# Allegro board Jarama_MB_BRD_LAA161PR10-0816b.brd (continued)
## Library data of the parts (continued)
Q347 = MMBT3904_SOT23-3
Q360 = SIS412DN-T1-GE3_POWERPAK8-5
Q361 = SI1553CDL-T1-GE3_SC70-6
R216 R1125 R1128 R1226 R1242 R1260 R1318-R1320 R1330 R1331 R1380 R1389 RA2 RA32 RH341 RH355 RH356 = R0603_0OHM
R541 = R_0805
R1221 R1222 R1372 RR2-RR5 RR7 RR8 RR12 RR13 RR15 RR16 = R0402_0OHM: signal model: R_0402NEW
R1322 RH340 = R0805_0OHM
RC92 RC96 = R0402_0OHM: signal model: R_0402NEW_R_0402NEW
RC94 = R_0402: signal model: R_0402NEW_R_0402NEW
RP3-RP5 RP21 RP22 = RP_0804_8P4R
RTCD1 = BAT54CW-7-F_SOT323-3
SW2 = SW_T3AL-23-Q-T-R_4P
T2 T123 T226-T231 T242-T246 T252 T254 T260 T261 T263-T289 = TPC12
U1 = RTS5227-GR_QFN32_4X4
U2 = W25Q32FVSSIQ_SO8
U4 = APA2605QAI-TRG_QFN20_4X4
U5 U682 U708-U710 U712 U713 = SN74AHC1G04DCKR_SOT23-5
U23 = PI3C3125LEX_TSSOP14
U34 = KB9012BF-A3_LFBGA_128P
U48 = W25Q64FVSSIQ_SO8
U635 = SN74LVC1G06DCKR_SC70-5
U636 = STM32F103RDY6TR_WLCSP_64P
U652 = AT97SC3204-X2A18-AB_TSSOP28
U663 = 74CBTLV3126BQ_DHVQFN14_2P5X3
U664 U715-U719 = TPS22966DPUR_SON14_2X3
U671 U677 = TXB0104PWR_TSSOP14
U672 UC1 = 74AUP1G07GW_TSSOP5
U673 = NCP4545IMNTWG_QFN18_3X3
U675 U678 U690 U691 U697 U698 UH5 = SN74AHC1G08DCKR_SC70-5
U676 = SN74CBT1G125DCKR_SC70-5
U679 = TXB0102YZPR_DSBGA_8P
U699 U700 = SN74AHC1G32DCKR_SC70-5
U714 = 1337GNLGI8_QFN16_3X3
U720 U721 U724 = TPS22965DSGR_SON8_2X2
U722 = PS8401ATQFN40GTR-A3_TQFN40_5X5
U725 = AH1806-W-7_SC59-3
UA1 = ALC5505_QFN48_7X7
UA2 = ALC3661-CG_MQFN48_6X6
UA3 = MAX9892ERTLFT_UCSP_6P
UCPU1 = SHARK-BAY-ULT_BGA_1168P-T
UD1 UD2 UD4-UD7 UD9 UD10 = MT41J256M16RE-15E-D_FBGA_96P
US1 US2 = TPS2543RTER_QFN16_3X3
Y1 YH1 = Y_CM31532768DZFT_2P
Y2 = Y_7A08000006_2P
Y3 = Y_Q13FC1350000200_2P
YA1 YH2 = Y_X3G024000DC1H_4P

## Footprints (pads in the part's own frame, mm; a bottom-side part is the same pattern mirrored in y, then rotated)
2N7002KDWH_SOT363-6
  oval 0.356x0.889 smd: 1(0,0) 2(0.65,0) 3(1.3,0) 4(1.3,1.6) 5(0.65,1.6) 6(0,1.6)
2N7002KW_SOT323-3
  oval 0.813x0.914 smd: 1(0,0) 2(0.65,1.6) 3(-0.65,1.6)
74AUP1G07GW_TSSOP5
  oval 0.381x1.346 smd: 1(0,0) 2(0.65,0) 3(1.3,0) 4(1.3,1.79) 5(0,1.79)
74CBTLV3126BQ_DHVQFN14_2P5X3
  oval 1.041x0.254 smd: 1(0,0) 7(2.95,0) 8(2.95,0.5) 14(0,0.5)
  oval 0.254x1.041 smd: 2(0.475,-0.975) 3(0.975,-0.975) 4(1.475,-0.975) 5(1.975,-0.975) 6(2.475,-0.975) 9(2.475,1.475) 10(1.975,1.475) 11(1.475,1.475) 12(0.975,1.475) 13(0.475,1.475)
  rect 1.499x0.991 smd: 15(1.475,0.25)
1337GNLGI8_QFN16_3X3
  oval 0.254x1.016 smd: 1(0,0) 2(0.5,0) 3(1,0) 4(1.5,0) 9(1.5,2.975) 10(1,2.975) 11(0.5,2.975) 12(0,2.975)
  oval 1.016x0.254 smd: 5(2.238,0.738) 6(2.238,1.238) 7(2.238,1.738) 8(2.238,2.238) 13(-0.738,2.238) 14(-0.738,1.738) 15(-0.738,1.238) 16(-0.738,0.738)
  rect 1.676x1.676 smd: 17(0.75,1.488)
ACES_50281-0120N-001_12P
  oval 0.787x2.007 smd: 1(0,0) 2(-1.25,0) 3(-2.5,0) 4(-3.75,0) 5(-5,0) 6(-6.25,0) 7(-7.5,0) 8(-8.75,0) 9(-10,0) 10(-11.25,0) 11(-12.5,0) 12(-13.75,0)
  rect 2.007x2.489 smd: 13(2.2,-4.05) 14(-15.95,-4.05)
ACES_50281-00501-001_5P-T
  oval 0.787x2.007 smd: 1(0,0) 2(1.25,0) 3(2.5,0) 4(3.75,0) 5(5,0)
  rect 2.007x2.489 smd: 6(7.2,-4.05) 7(-2.2,-4.05)
ACES_50406-02071-001_20P
  oval 0.254x1.295 smd: 1(0,0) 2(0.5,0) 3(1,0) 4(1.5,0) 5(2,0) 6(2.5,0) 7(3,0) 8(3.5,0) 9(4,0) 10(4.5,0) 11(5,0) 12(5.5,0) 13(6,0) 14(6.5,0) 15(7,0) 16(7.5,0) 17(8,0) 18(8.5,0) 19(9,0) 20(9.5,0)
  rect 1.194x2.692 smd: 21(-2.4,1.95) 22(11.9,1.95)
  rect 2.311x1.295 smd: 23(0.85,3.9) 24(8.65,3.9)
ACES_50696-02001-001_20P-T
  oval 0.305x0.787 smd: 1(0,0) 2(0.5,0) 3(1,0) 4(1.5,0) 5(2,0) 6(2.5,0) 7(3,0) 8(3.5,0) 9(4,0) 10(4.5,0) 11(5,0) 12(5.5,0) 13(6,0) 14(6.5,0) 15(7,0) 16(7.5,0) 17(8,0) 18(8.5,0) 19(9,0) 20(9.5,0)
  rect 0.406x0.787 smd: 21(-1,-2.5) 22(10.5,-2.5)
ACES_51522-00401-001_4P-T
  oval 0.305x1.295 smd: 1(0,0) 2(-0.5,0) 3(-1,0) 4(-1.5,0)
  rect 2.489x1.905 smd: 5(2.15,-3.3) 6(-3.65,-3.3)
ACES_51522-01001-001_10P
  oval 0.305x1.295 smd: 1(0,0) 2(0.5,0) 3(1,0) 4(1.5,0) 5(2,0) 6(2.5,0) 7(3,0) 8(3.5,0) 9(4,0) 10(4.5,0)
  rect 2.489x1.905 smd: 11(-2.15,-3.3) 12(6.65,-3.3)
ACES_51522-01201-001_12P
  oval 0.305x1.295 smd: 1(0,0) 2(0.5,0) 3(1,0) 4(1.5,0) 5(2,0) 6(2.5,0) 7(3,0) 8(3.5,0) 9(4,0) 10(4.5,0) 11(5,0) 12(5.5,0)
  rect 2.489x1.905 smd: 13(-2.15,-3.3) 14(7.65,-3.3)
ACON_HMR2G-AK120C_19P-T
  round 0.813 hole 0.559: 1(0,0) 2(-0.5,-1.55) 3(-1,0) 4(-1.5,-1.55) 5(-2,0) 6(-2.5,-1.55) 7(-3,0) 8(-3.5,-1.55) 9(-4,0) 10(-4.5,-1.55) 11(-5,0) 12(-5.5,-1.55) 13(-6,0) 14(-6.5,-1.55) 15(-7,0) 16(-7.5,-1.55) 17(-8,0) 18(-8.5,-1.55) 19(-9,0)
  oval 1.397x2.997 hole 0.787x2.388: 20(-11.75,-0.18) 21(2.75,-0.18)
  oval 1.397x2.794 hole 0.787x2.21: 22(-13.25,-7.53) 23(4.25,-7.53)
AH1806-W-7_SC59-3
  oval 0.787x0.991 smd: 1(0,0) 2(-0.95,-2.4) 3(0.95,-2.4)
ALC3661-CG_MQFN48_6X6
  oval 0.203x1.041 smd: 1(0,0) 2(0.4,0) 3(0.8,0) 4(1.2,0) 5(1.6,0) 6(2,0) 7(2.4,0) 8(2.8,0) 9(3.2,0) 10(3.6,0) 11(4,0) 12(4.4,0) 25(4.4,5.95) 26(4,5.95) 27(3.6,5.95) 28(3.2,5.95) 29(2.8,5.95) 30(2.4,5.95) 31(2,5.95) 32(1.6,5.95) 33(1.2,5.95) 34(0.8,5.95) 35(0.4,5.95) 36(0,5.95)
  oval 1.041x0.203 smd: 13(5.175,0.775) 14(5.175,1.175) 15(5.175,1.575) 16(5.175,1.975) 17(5.175,2.375) 18(5.175,2.775) 19(5.175,3.175) 20(5.175,3.575) 21(5.175,3.975) 22(5.175,4.375) 23(5.175,4.775) 24(5.175,5.175) 37(-0.775,5.175) 38(-0.775,4.775) 39(-0.775,4.375) 40(-0.775,3.975) 41(-0.775,3.575) 42(-0.775,3.175) 43(-0.775,2.775) 44(-0.775,2.375) 45(-0.775,1.975) 46(-0.775,1.575) 47(-0.775,1.175) 48(-0.775,0.775)
  rect 4.394x4.394 smd: 49(2.2,2.975)
ALC5505_QFN48_7X7
  oval 0.254x1.041 smd: 1(0,0) 2(0.5,0) 3(1,0) 4(1.5,0) 5(2,0) 6(2.5,0) 7(3,0) 8(3.5,0) 9(4,0) 10(4.5,0) 11(5,0) 12(5.5,0) 25(5.5,6.95) 26(5,6.95) 27(4.5,6.95) 28(4,6.95) 29(3.5,6.95) 30(3,6.95) 31(2.5,6.95) 32(2,6.95) 33(1.5,6.95) 34(1,6.95) 35(0.5,6.95) 36(0,6.95)
  oval 1.041x0.254 smd: 13(6.225,0.725) 14(6.225,1.225) 15(6.225,1.725) 16(6.225,2.225) 17(6.225,2.725) 18(6.225,3.225) 19(6.225,3.725) 20(6.225,4.225) 21(6.225,4.725) 22(6.225,5.225) 23(6.225,5.725) 24(6.225,6.225) 37(-0.725,6.225) 38(-0.725,5.725) 39(-0.725,5.225) 40(-0.725,4.725) 41(-0.725,4.225) 42(-0.725,3.725) 43(-0.725,3.225) 44(-0.725,2.725) 45(-0.725,2.225) 46(-0.725,1.725) 47(-0.725,1.225) 48(-0.725,0.725)
  rect 5.461x5.461 smd: 49(2.75,3.475)
AO3419L_SOT23-3
  oval 1.016x1.524 smd: 1(0,0) 2(0.965,2.083) 3(-0.965,2.083)
AO4407AL_SO8
  oval 0.635x1.854 smd: 1(0,0) 2(1.27,0) 3(2.54,0) 4(3.81,0) 5(3.81,5.165) 6(2.54,5.165) 7(1.27,5.165) 8(0,5.165)
APA2605QAI-TRG_QFN20_4X4
  oval 0.254x1.041 smd: 1(0,0) 2(0.5,0) 3(1,0) 4(1.5,0) 5(2,0) 11(2,3.95) 12(1.5,3.95) 13(1,3.95) 14(0.5,3.95) 15(0,3.95)
  oval 1.041x0.254 smd: 6(2.975,0.975) 7(2.975,1.475) 8(2.975,1.975) 9(2.975,2.475) 10(2.975,2.975) 16(-0.975,2.975) 17(-0.975,2.475) 18(-0.975,1.975) 19(-0.975,1.475) 20(-0.975,0.975)
  rect 2.261x2.261 smd: 21(1,1.975)
AT97SC3204-X2A18-AB_TSSOP28
  oval 0.381x1.626 smd: 1(0,0) 2(0.65,0) 3(1.3,0) 4(1.95,0) 5(2.6,0) 6(3.25,0) 7(3.9,0) 8(4.55,0) 9(5.2,0) 10(5.85,0) 11(6.5,0) 12(7.15,0) 13(7.8,0) 14(8.45,0) 15(8.45,5.8) 16(7.8,5.8) 17(7.15,5.8) 18(6.5,5.8) 19(5.85,5.8) 20(5.2,5.8) 21(4.55,5.8) 22(3.9,5.8) 23(3.25,5.8) 24(2.6,5.8) 25(1.95,5.8) 26(1.3,5.8) 27(0.65,5.8) 28(0,5.8)
AZ1045-04F_DFN2510P10E-10-9
  oval 0.254x0.686 smd: 1(0,0) 2(0.5,0) 4(1.5,0) 5(2,0) 6(2,0.875) 7(1.5,0.875) 8(0.5,0.875) 9(0,0.875)
  oval 0.406x1.549 smd: 3(1,0.437)
AZ1065-06QPRDG_MSOP8
  oval 0.381x1.575 smd: 1(0,0) 2(0.65,0) 3(1.3,0) 4(1.95,0) 5(1.95,4.35) 6(1.3,4.35) 7(0.65,4.35) 8(0,4.35)
BAT54CW-7-F_SOT323-3
  oval 0.711x0.889 smd: 1(0,0) 2(-0.65,-1.9) 3(0.65,-1.9)
BAT54CW_SOT323-3
  oval 0.61x0.559 smd: 1(0,0) 2(-0.65,-1.85) 3(0.65,-1.85)
BAT54HT1G_SOD323-2
  rect 0.635x0.838 smd: 1(0,0) 2(2.22,0)
BAT1000-7-F_SOT23-3
  oval 1.016x1.524 smd: 1(0,0) 2(0.965,2.083) 3(-0.965,2.083)
BJ_CR2016-L01-JHLF_2P
  rect 1.245x2.489 smd: 1(0,0) 2(6.25,0)
BQ24715RGRR_QFN20_3P5X3P5
  oval 0.254x1.041 smd: 1(0,0) 2(0.5,0) 3(1,0) 4(1.5,0) 5(2,0) 11(2,3.45) 12(1.5,3.45) 13(1,3.45) 14(0.5,3.45) 15(0,3.45)
  oval 1.041x0.254 smd: 6(2.725,0.725) 7(2.725,1.225) 8(2.725,1.725) 9(2.725,2.225) 10(2.725,2.725) 16(-0.725,2.725) 17(-0.725,2.225) 18(-0.725,1.725) 19(-0.725,1.225) 20(-0.725,0.725)
  rect 2.057x2.057 smd: 21(1,1.725)
C_0402
  rect 0.508x0.559 smd: 1(0,0) 2(0.914,0)
C_0603
  rect 0.635x0.889 smd: 1(0,0) 2(1.397,0)
C_0805
  rect 0.813x1.397 smd: 1(0,0) 2(1.702,0)
C_1206
  rect 1.016x1.651 smd: 1(0,0) 2(2.667,0)
C_A1
  rect 1.346x1.499 smd: 1(0,0) 2(2.45,0)
C_B
  rect 1.549x2.464 smd: 1(0,0) 2(3.378,0)
C_B2
  rect 1.346x2.692 smd: 1(0,0) 2(-2.75,0)
CSD87312Q3E_SON8-4
  rect 2.388x0.66 smd: 1(0,0)
  rect 0.432x0.66 smd: 2(0.975,2.95)
  rect 1.753x0.66 smd: 3(-0.325,2.95)
  custom 0.475x0.475 smd: 4(0,1.475)
CSD87330Q3D_SON8-7
  oval 1.092x0.66 smd: 1(0,0)
  oval 0.432x0.66 smd: 2(0.975,0) 3(1.625,0) 4(1.625,2.95) 5(0.975,2.95) 6(0.325,2.95) 7(-0.325,2.95)
  custom 0.475x0.475 smd: 8(0.65,1.475)
CSD97374CQ4M_SON8_3P5X4P5
  oval 0.203x0.889 smd: 1(0,0) 2(0.4,0) 3(0.8,0) 6(0.8,3.5) 7(0.4,3.5) 8(0,3.5)
  custom 0.225x0.225 smd: 4(2.2,0.262) 5(2.2,3.238)
  rect 4.039x2.21 smd: 9(1.6,1.75)
CVILU_CI4304M2HR0-NH_4P
  oval 0.787x2.007 smd: 1(0,0) 2(1.25,0) 3(2.5,0) 4(3.75,0)
  rect 2.007x2.489 smd: 5(-2.2,-4.05) 6(5.95,-4.05)
CYNTE_PCMB063T-2R2MS_2P
  rect 2.362x3.505 smd: 1(0,0) 2(6.05,0)
CYNTE_PCMC063T-R68MN_2P
  rect 1.854x3.505 smd: 1(0,0) 2(5.55,0)
CYNTE_PG031B-4R7MS_2P
  rect 0.889x1.194 smd: 1(0,0) 2(2.2,0)
DB2J31400L_SOD323-2
  rect 0.991x1.092 smd: 1(0,0)
  rect 0.991x0.889 smd: 2(2.1,0)
DMN66D0LDW-7_SOT363-6
  oval 0.432x0.61 smd: 1(0,0) 2(0.65,0) 3(1.3,0) 4(1.3,1.9) 5(0.65,1.9) 6(0,1.9)
E-T_6705K-Y18N-00L_18P
  oval 0.305x1.092 smd: 1(0,0) 2(-0.5,0) 3(-1,0) 4(-1.5,0) 5(-2,0) 6(-2.5,0) 7(-3,0) 8(-3.5,0) 9(-4,0) 10(-4.5,0) 11(-5,0) 12(-5.5,0) 13(-6,0) 14(-6.5,0) 15(-7,0) 16(-7.5,0) 17(-8,0) 18(-8.5,0)
  rect 0.991x2.007 smd: 19(2.1,-3.15) 20(-10.6,-3.15)
F_1812L075-24DR
  rect 0.889x3.15 smd: 1(0,0) 2(4.35,0)
F_SMD1812P110TF
  rect 0.889x3.15 smd: 1(0,0) 2(4.35,0)
FDV301N-G_SOT23-3
  oval 1.016x1.524 smd: 1(0,0) 2(0.965,2.083) 3(-0.965,2.083)
FIDUCIAL_C40M80
  round 1.016 smd: 1(0,0)
FOX_GS73091-10272-7H_9P-T
  rect 0.66x5.004 smd: 1(0,0) 2(-1.5,0) 3(-3,0) 4(-4.5,0) 5(-6,0) 6(-7.5,0) 7(-9,0) 8(-10.5,0) 9(-12,0)
  rect 2.489x2.997 smd: 10(-14.5,4.45) 11(2.5,4.45)
G5616ARZ1U_TQFN20_3X3
  oval 0.203x1.016 smd: 1(0,0) 2(0.4,0) 3(0.8,0) 4(1.2,0) 5(1.6,0) 11(1.6,2.975) 12(1.2,2.975) 13(0.8,2.975) 14(0.4,2.975) 15(0,2.975)
  oval 1.016x0.203 smd: 6(2.288,0.688) 7(2.288,1.088) 8(2.288,1.488) 9(2.288,1.888) 10(2.288,2.288) 16(-0.688,2.288) 17(-0.688,1.888) 18(-0.688,1.488) 19(-0.688,1.088) 20(-0.688,0.688)
  rect 1.6x1.6 smd: 21(0.8,1.488)
H_1P6N
  round 1.6 hole 1.6 unplated: (0,0)
H_2P4
  round 2.896 hole 2.388: 1(0,0)
H_2P4X1P6N
  oval 2.388x1.6 hole 2.388x1.6 unplated: (0,0)
H_3P0
  round 3.505 hole 2.997: 1(0,0)
H_3P3
  round 3.81 hole 3.302: 1(0,0)
H_3P9
  round 4.42 hole 3.912: 1(0,0)
HB_A510810-SCHR21_8P
  oval 0.305x1.092 smd: 1(0,0) 2(-0.5,0) 3(-1,0) 4(-1.5,0) 5(-2,0) 6(-2.5,0) 7(-3,0) 8(-3.5,0)
  rect 0.406x0.787 smd: 9(-4.5,-2.65) 10(1,-2.65)
HB_A520620-SCHR22_6P
  oval 0.305x1.295 smd: 1(0,0) 2(0.5,0) 3(1,0) 4(1.5,0) 5(2,0) 6(2.5,0)
  rect 2.489x1.905 smd: 7(-2.15,-3.3) 8(4.65,-3.3)
HB_A531515-SCHR21_15P-T
  oval 0.305x1.245 smd: 1(0,0) 2(0.5,0) 3(1,0) 4(1.5,0) 5(2,0) 6(2.5,0) 7(3,0) 8(3.5,0) 9(4,0) 10(4.5,0) 11(5,0) 12(5.5,0) 13(6,0) 14(6.5,0) 15(7,0)
  rect 0.991x2.007 smd: 16(-2.1,-2.875) 17(9.1,-2.875)
IP4223CZ6_SO6
  oval 0.508x1.422 smd: 1(0,0) 2(0.95,0) 3(1.9,0) 4(1.9,2.35) 5(0.95,2.35) 6(0,2.35)
JAE_SM3ZS067U215ALL_75P-T
  round 1.092 hole 1.092 unplated: (-0.75,-5.225)
  round 1.6 hole 1.6 unplated: (19.25,-5.225)
  oval 0.305x1.549 smd: 1(0,0) 2(0.25,-7.45) 3(0.5,0) 4(0.75,-7.45) 5(1,0) 6(1.25,-7.45) 7(1.5,0) 8(1.75,-7.45) 9(2,0) 10(2.25,-7.45) 11(2.5,0) 12(2.75,-7.45) 13(3,0) 14(3.25,-7.45) 15(3.5,0) 16(3.75,-7.45) 17(4,0) 18(4.25,-7.45) 19(4.5,0) 20(4.75,-7.45) 21(5,0) 22(5.25,-7.45) 23(5.5,0) 24(5.75,-7.45) 25(6,0) 26(6.25,-7.45) 27(6.5,0) 28(6.75,-7.45) 29(7,0) 30(7.25,-7.45) 31(7.5,0) 32(7.75,-7.45) 33(8,0) 34(8.25,-7.45) 35(8.5,0) 36(8.75,-7.45) 37(9,0) 38(9.25,-7.45) 39(9.5,0) 40(9.75,-7.45) 41(10,0) 42(10.25,-7.45) 43(10.5,0) 44(10.75,-7.45) 45(11,0) 46(11.25,-7.45) 47(11.5,0) 48(11.75,-7.45) 49(12,0) 50(12.25,-7.45) 51(12.5,0) 52(12.75,-7.45) 53(13,0) 54(13.25,-7.45) 55(13.5,0) 56(13.75,-7.45) 57(14,0) 58(14.25,-7.45) 59(14.5,0) 60(14.75,-7.45) 61(15,0) 62(15.25,-7.45) 63(15.5,0) 64(15.75,-7.45) 65(16,0) 66(16.25,-7.45) 67(16.5,0) 68(16.75,-7.45) 69(17,0) 70(17.25,-7.45) 71(17.5,0) 72(17.75,-7.45) 73(18,0) 74(18.25,-7.45) 75(18.5,0)
  rect 1.194x2.743 smd: 76(19.6,-0.725) 77(-1.1,-0.725)
JUMP_43X39
  custom 0.191x0.191 smd: 1(0,0) 2(0.914,0)
JUMP_43X79
  custom 0.188x0.188 smd: 1(0,0) 2(1.1,0)
JUMP_43X118
  custom 0.187x0.187 smd: 1(0,0) 2(1.1,0)
KB9012BF-A3_LFBGA_128P
  round 0.254 smd: A1(0,0) A2(0.5,0) A3(1,0) A4(1.5,0) A5(2,0) A6(2.5,0) A7(3,0) A8(3.5,0) A9(4,0) A10(4.5,0) A11(5,0) A12(5.5,0) A13(6,0) B1(0,-0.5) B2(0.5,-0.5) B3(1,-0.5) B4(1.5,-0.5) B5(2,-0.5) B6(2.5,-0.5) B7(3,-0.5) B8(3.5,-0.5) B9(4,-0.5) B10(4.5,-0.5) B11(5,-0.5) B12(5.5,-0.5) B13(6,-0.5) C1(0,-1) C2(0.5,-1) C12(5.5,-1) C13(6,-1) D1(0,-1.5) D2(0.5,-1.5) D4(1.5,-1.5) D5(2,-1.5) D6(2.5,-1.5) D7(3,-1.5) D8(3.5,-1.5) D9(4,-1.5) D10(4.5,-1.5) D12(5.5,-1.5) D13(6,-1.5) E1(0,-2) E2(0.5,-2) E4(1.5,-2) E5(2,-2) E6(2.5,-2) E7(3,-2) E8(3.5,-2) E9(4,-2) E10(4.5,-2) E12(5.5,-2) E13(6,-2) F1(0,-2.5) F2(0.5,-2.5) F4(1.5,-2.5) F5(2,-2.5) F9(4,-2.5) F10(4.5,-2.5) F12(5.5,-2.5) F13(6,-2.5) G1(0,-3) G2(0.5,-3) G4(1.5,-3) G5(2,-3) G9(4,-3) G10(4.5,-3) G12(5.5,-3) G13(6,-3) H1(0,-3.5) H2(0.5,-3.5) H4(1.5,-3.5) H5(2,-3.5) H9(4,-3.5) H10(4.5,-3.5) H12(5.5,-3.5) H13(6,-3.5) J1(0,-4) J2(0.5,-4) J4(1.5,-4) J5(2,-4) J6(2.5,-4) J7(3,-4) J8(3.5,-4) J9(4,-4) J10(4.5,-4) J12(5.5,-4) J13(6,-4) K1(0,-4.5) K2(0.5,-4.5) K4(1.5,-4.5) K5(2,-4.5) K6(2.5,-4.5) K7(3,-4.5) K8(3.5,-4.5) K9(4,-4.5) K10(4.5,-4.5) K12(5.5,-4.5) K13(6,-4.5) L1(0,-5) L2(0.5,-5) L12(5.5,-5) L13(6,-5) M1(0,-5.5) M2(0.5,-5.5) M3(1,-5.5) M4(1.5,-5.5) M5(2,-5.5) M6(2.5,-5.5) M7(3,-5.5) M8(3.5,-5.5) M9(4,-5.5) M10(4.5,-5.5) M11(5,-5.5) M12(5.5,-5.5) M13(6,-5.5) N1(0,-6) N2(0.5,-6) N3(1,-6) N4(1.5,-6) N5(2,-6) N6(2.5,-6) N7(3,-6) N8(3.5,-6) N9(4,-6) N10(4.5,-6) N11(5,-6) N12(5.5,-6) N13(6,-6)
KC_FBMA-L11-160808-800LMT_2P
  rect 0.889x1.092 smd: 1(0,0) 2(1.5,0)
KC_FBMA-L11-201209-121LMA50_2P
  rect 0.991x1.702 smd: 1(0,0) 2(1.5,0)
KC_FBMA-L11-453215800LMA90T_2P
  rect 1.803x3.404 smd: 1(0,0) 2(3.8,0)
LCN_DAN08-52216-0100_52P
  round 0.991 hole 0.991 unplated: (-26.2,-3) (2.6,-3)
  oval 0.406x1.6 smd: 1(0,0) 3(-0.8,0) 5(-1.6,0) 7(-2.4,0) 9(-3.2,0) 11(-4,0) 13(-4.8,0) 15(-5.6,0) 17(-9.6,0) 19(-10.4,0) 21(-11.2,0) 23(-12,0) 25(-12.8,0) 27(-13.6,0) 29(-14.4,0) 31(-15.2,0) 33(-16,0) 35(-16.8,0) 37(-17.6,0) 39(-18.4,0) 41(-19.2,0) 43(-20,0) 45(-20.8,0) 47(-21.6,0) 49(-22.4,0) 51(-23.2,0)
  oval 0.61x1.397 hole 0.406x0.787: 2(-0.4,-1.65) 4(-1.2,-1.65) 6(-2,-1.65) 8(-2.8,-1.65) 10(-3.6,-1.65) 12(-4.4,-1.65) 14(-5.2,-1.65) 16(-6,-1.65) 18(-10,-1.65) 20(-10.8,-1.65) 22(-11.6,-1.65) 24(-12.4,-1.65) 26(-13.2,-1.65) 28(-14,-1.65) 30(-14.8,-1.65) 32(-15.6,-1.65) 34(-16.4,-1.65) 36(-17.2,-1.65) 38(-18,-1.65) 40(-18.8,-1.65) 42(-19.6,-1.65) 44(-20.4,-1.65) 46(-21.2,-1.65) 48(-22,-1.65) 50(-22.8,-1.65) 52(-23.6,-1.65)
  oval 1.27x2.972 hole 0.508x2.21: 53(3.1,-6.2) 54(-26.7,-6.2)
LED_LTW-C193TS5_2P
  rect 0.787x0.787 smd: 1(0,0) 2(1.5,0)
LOTES_APCI0019-P001A01_67P-T
  round 1.092 hole 1.092 unplated: (-0.75,-5.275)
  round 1.6 hole 1.6 unplated: (19.25,-5.275)
  oval 0.305x1.549 smd: 1(0,0) 2(0.25,-7.55) 3(0.5,0) 4(0.75,-7.55) 5(1,0) 6(1.25,-7.55) 7(1.5,0) 8(1.75,-7.55) 9(2,0) 10(2.25,-7.55) 11(2.5,0) 12(2.75,-7.55) 13(3,0) 14(3.25,-7.55) 15(3.5,0) 16(3.75,-7.55) 17(4,0) 18(4.25,-7.55) 19(4.5,0) 20(4.75,-7.55) 21(5,0) 22(5.25,-7.55) 23(5.5,0) 24(7.75,-7.55) 25(8,0) 26(8.25,-7.55) 27(8.5,0) 28(8.75,-7.55) 29(9,0) 30(9.25,-7.55) 31(9.5,0) 32(9.75,-7.55) 33(10,0) 34(10.25,-7.55) 35(10.5,0) 36(10.75,-7.55) 37(11,0) 38(11.25,-7.55) 39(11.5,0) 40(11.75,-7.55) 41(12,0) 42(12.25,-7.55) 43(12.5,0) 44(12.75,-7.55) 45(13,0) 46(13.25,-7.55) 47(13.5,0) 48(13.75,-7.55) 49(14,0) 50(14.25,-7.55) 51(14.5,0) 52(14.75,-7.55) 53(15,0) 54(15.25,-7.55) 55(15.5,0) 56(15.75,-7.55) 57(16,0) 58(16.25,-7.55) 59(16.5,0) 60(16.75,-7.55) 61(17,0) 62(17.25,-7.55) 63(17.5,0) 64(17.75,-7.55) 65(18,0) 66(18.25,-7.55) 67(18.5,0)
  rect 1.194x2.743 smd: 68(-1.1,-0.775) 69(19.6,-0.775)
MAG_MMD06CZER15MG_4P
  custom 0.686x0.686 smd: 1(0,0) 4(8.509,0)
  rect 2.362x0.508 smd: 2(1.448,0) 3(7.061,0)
MAX9892ERTLFT_UCSP_6P
  round 0.267 smd: A1(0,0) A2(0.5,0) A3(1,0) B1(0,-0.5) B2(0.5,-0.5) B3(1,-0.5)
MDV1524URH_PDFN33-8-5
  oval 0.406x0.61 smd: 1(0,0) 2(0.65,0) 3(1.3,0) 4(1.95,0)
  custom 0.65x0.65 smd: 5(0.975,1.475)
MDV1528URH_PDFN33-8-5
  oval 0.406x0.61 smd: 1(0,0) 2(0.65,0) 3(1.3,0) 4(1.95,0)
  custom 0.65x0.65 smd: 5(0.975,1.475)
MMBT3904_SOT23-3
  oval 1.016x1.524 smd: 1(0,0) 2(0.965,2.083) 3(-0.965,2.083)
MMST3904-7-F_SOT323-3
  oval 0.711x0.889 smd: 1(0,0) 2(0.65,1.9) 3(-0.65,1.9)
MT41J256M16RE-15E-D_FBGA_96P
  round 0.343 smd: A1(0,0) A2(0.8,0) A3(1.6,0) A7(4.8,0) A8(5.6,0) A9(6.4,0) B1(0,-0.8) B2(0.8,-0.8) B3(1.6,-0.8) B7(4.8,-0.8) B8(5.6,-0.8) B9(6.4,-0.8) C1(0,-1.6) C2(0.8,-1.6) C3(1.6,-1.6) C7(4.8,-1.6) C8(5.6,-1.6) C9(6.4,-1.6) D1(0,-2.4) D2(0.8,-2.4) D3(1.6,-2.4) D7(4.8,-2.4) D8(5.6,-2.4) D9(6.4,-2.4) E1(0,-3.2) E2(0.8,-3.2) E3(1.6,-3.2) E7(4.8,-3.2) E8(5.6,-3.2) E9(6.4,-3.2) F1(0,-4) F2(0.8,-4) F3(1.6,-4) F7(4.8,-4) F8(5.6,-4) F9(6.4,-4) G1(0,-4.8) G2(0.8,-4.8) G3(1.6,-4.8) G7(4.8,-4.8) G8(5.6,-4.8) G9(6.4,-4.8) H1(0,-5.6) H2(0.8,-5.6) H3(1.6,-5.6) H7(4.8,-5.6) H8(5.6,-5.6) H9(6.4,-5.6) J1(0,-6.4) J2(0.8,-6.4) J3(1.6,-6.4) J7(4.8,-6.4) J8(5.6,-6.4) J9(6.4,-6.4) K1(0,-7.2) K2(0.8,-7.2) K3(1.6,-7.2) K7(4.8,-7.2) K8(5.6,-7.2) K9(6.4,-7.2) L1(0,-8) L2(0.8,-8) L3(1.6,-8) L7(4.8,-8) L8(5.6,-8) L9(6.4,-8) M1(0,-8.8) M2(0.8,-8.8) M3(1.6,-8.8) M7(4.8,-8.8) M8(5.6,-8.8) M9(6.4,-8.8) N1(0,-9.6) N2(0.8,-9.6) N3(1.6,-9.6) N7(4.8,-9.6) N8(5.6,-9.6) N9(6.4,-9.6) P1(0,-10.4) P2(0.8,-10.4) P3(1.6,-10.4) P7(4.8,-10.4) P8(5.6,-10.4) P9(6.4,-10.4) R1(0,-11.2) R2(0.8,-11.2) R3(1.6,-11.2) R7(4.8,-11.2) R8(5.6,-11.2) R9(6.4,-11.2) T1(0,-12) T2(0.8,-12) T3(1.6,-12) T7(4.8,-12) T8(5.6,-12) T9(6.4,-12)
MURAT_BLM15AG102SN1D_2P
  rect 0.457x0.508 smd: 1(0,0) 2(0.85,0)
MURAT_BLM18BA220SN1D_2P
  oval 0.66x1.041 smd: 1(0,0) 2(1.2,0)
MURAT_BLM18PG181SN1D_L0603_2P
  rect 0.66x1.041 smd: 1(0,0) 2(1.2,0)
MURAT_BLM21PG600SN1D_2P
  rect 0.991x1.753 smd: 1(0,0) 2(1.5,0)
MURAT_DLW21HN900SQ2L_4P
  rect 0.889x0.356 smd: 1(0,0) 2(1.7,0) 3(1.7,0.85) 4(0,0.85)
MURAT_DLW21SN670HQ2L_4P
  rect 0.889x0.406 smd: 1(0,0) 2(1.7,0) 3(1.7,0.8) 4(0,0.8)
MURAT_DLW21SN900HQ2L_0805_4P
  rect 0.889x0.356 smd: 1(0,0) 2(1.7,0) 3(1.7,0.85) 4(0,0.85)
MURAT_LQM2MPN2R2NG0L_2P
  rect 0.787x1.803 smd: 1(0,0) 2(1.6,0)
NCP4545IMNTWG_QFN18_3X3
  oval 0.254x0.94 smd: 1(0,0) 2(0.5,0) 3(1,0) 4(1.5,0) 10(1.5,3.05) 11(1,3.05) 12(0.5,3.05) 13(0,3.05)
  oval 0.94x0.254 smd: 5(2.275,0.525) 6(2.275,1.025) 7(2.275,1.525) 8(2.275,2.025) 9(2.275,2.525) 14(-0.775,2.525) 15(-0.775,2.025) 16(-0.775,1.525) 17(-0.775,1.025) 18(-0.775,0.525)
  rect 1.854x1.854 smd: 19(0.75,1.525)
NCQF0_MB_SUP_BRK
  custom 1.25x1.25 smd: 1(0,0)
PESD5V0U2BT_SOT23-3
  oval 1.016x1.524 smd: 1(0,0) 2(0.965,2.083) 3(-0.965,2.083)
PESD24VS2UT_SOT23-3
  oval 1.016x1.524 smd: 1(0,0) 2(0.965,2.083) 3(-0.965,2.083)
PI3C3125LEX_TSSOP14
  oval 0.381x1.626 smd: 1(0,0) 2(0.65,0) 3(1.3,0) 4(1.95,0) 5(2.6,0) 6(3.25,0) 7(3.9,0) 8(3.9,5.8) 9(3.25,5.8) 10(2.6,5.8) 11(1.95,5.8) 12(1.3,5.8) 13(0.65,5.8) 14(0,5.8)
PJDLC05_SOT23-3
  oval 1.016x1.524 smd: 1(0,0) 2(0.965,2.083) 3(-0.965,2.083)
PJDLC05C_SOT23-3
  oval 1.016x1.524 smd: 1(0,0) 2(0.965,2.083) 3(-0.965,2.083)
PS8401ATQFN40GTR-A3_TQFN40_5X5
  oval 0.203x1.016 smd: 1(0,0) 2(0.4,0) 3(0.8,0) 4(1.2,0) 5(1.6,0) 6(2,0) 7(2.4,0) 8(2.8,0) 9(3.2,0) 10(3.6,0) 21(3.6,4.975) 22(3.2,4.975) 23(2.8,4.975) 24(2.4,4.975) 25(2,4.975) 26(1.6,4.975) 27(1.2,4.975) 28(0.8,4.975) 29(0.4,4.975) 30(0,4.975)
  oval 1.016x0.203 smd: 11(4.288,0.688) 12(4.288,1.088) 13(4.288,1.488) 14(4.288,1.888) 15(4.288,2.288) 16(4.288,2.688) 17(4.288,3.088) 18(4.288,3.488) 19(4.288,3.888) 20(4.288,4.288) 31(-0.688,4.288) 32(-0.688,3.888) 33(-0.688,3.488) 34(-0.688,3.088) 35(-0.688,2.688) 36(-0.688,2.288) 37(-0.688,1.888) 38(-0.688,1.488) 39(-0.688,1.088) 40(-0.688,0.688)
  rect 3.607x3.607 smd: 41(1.8,2.488)
R0402_0OHM
  rect 0.508x0.559 smd: 1(0,0) 2(0.914,0)
R0603_0OHM
  rect 0.635x0.889 smd: 1(0,0) 2(1.397,0)
R0805_0OHM
  rect 0.813x1.397 smd: 1(0,0) 2(1.702,0)
R_0402
  rect 0.508x0.559 smd: 1(0,0) 2(0.914,0)
R_0603
  rect 0.635x0.889 smd: 1(0,0) 2(1.397,0)
R_0805
  rect 0.813x1.397 smd: 1(0,0) 2(1.702,0)
R_1206
  rect 1.016x1.651 smd: 1(0,0) 2(2.667,0)
R_1206_4P-D
  custom 0.445x0.445 smd: 1(0,0) 4(5.004,0)
  custom 0.114x0.114 smd: 2(1.194,0) 3(3.81,0)
RB751V-40_SOD323-2
  rect 0.787x0.889 smd: 1(0,0) 2(2.14,0)
RB751V-40GTE-17_SOD323-2
  rect 0.787x0.889 smd: 1(0,0) 2(2.1,0)
RP_0804_8P4R
  oval 0.66x0.254 smd: 1(0,0) 2(0,-0.5) 3(0,-1) 4(0,-1.5) 5(1.15,-1.5) 6(1.15,-1) 7(1.15,-0.5) 8(1.15,0)
RTS5227-GR_QFN32_4X4
  oval 0.203x0.914 smd: 1(0,0) 2(0.4,0) 3(0.8,0) 4(1.2,0) 5(1.6,0) 6(2,0) 7(2.4,0) 8(2.8,0) 17(2.8,4.077) 18(2.4,4.077) 19(2,4.077) 20(1.6,4.077) 21(1.2,4.077) 22(0.8,4.077) 23(0.4,4.077) 24(0,4.077)
  oval 0.914x0.203 smd: 9(3.438,0.639) 10(3.438,1.039) 11(3.438,1.438) 12(3.438,1.838) 13(3.438,2.239) 14(3.438,2.639) 15(3.438,3.039) 16(3.438,3.438) 25(-0.639,3.438) 26(-0.639,3.039) 27(-0.639,2.639) 28(-0.639,2.239) 29(-0.639,1.838) 30(-0.639,1.438) 31(-0.639,1.039) 32(-0.639,0.639)
  rect 2.692x2.692 smd: 33(1.4,2.039)
SAMTE_BSH-030-01-L-D-A_60P
  round 1.016 hole 1.016 unplated: (-2.81,5.53) (17.316,5.53)
  oval 0.279x2.261 smd: 1(0,0) 2(0,5.728) 3(0.5,0) 4(0.5,5.728) 5(1,0) 6(1,5.728) 7(1.5,0) 8(1.5,5.728) 9(2,0) 10(2,5.728) 11(2.5,0) 12(2.5,5.728) 13(3,0) 14(3,5.728) 15(3.5,0) 16(3.5,5.728) 17(4,0) 18(4,5.728) 19(4.5,0) 20(4.5,5.728) 21(5,0) 22(5,5.728) 23(5.5,0) 24(5.5,5.728) 25(6,0) 26(6,5.728) 27(6.5,0) 28(6.5,5.728) 29(7,0) 30(7,5.728) 31(7.5,0) 32(7.5,5.728) 33(8,0) 34(8,5.728) 35(8.5,0) 36(8.5,5.728) 37(9,0) 38(9,5.728) 39(9.5,0) 40(9.5,5.728) 41(10,0) 42(10,5.728) 43(10.5,0) 44(10.5,5.728) 45(11,0) 46(11,5.728) 47(11.5,0) 48(11.5,5.728) 49(12,0) 50(12,5.728) 51(12.5,0) 52(12.5,5.728) 53(13,0) 54(13,5.728) 55(13.5,0) 56(13.5,5.728) 57(14,0) 58(14,5.728) 59(14.5,0) 60(14.5,5.728)
SDMK0340L-7-F_SOD323-2
  rect 1.346x0.66 smd: 1(0,0) 2(2.4,0)
SHARK-BAY-ULT_BGA_1168P-T
  round 0.508 smd: A3(-1.137,0) A62(-38.036,0) AW1(0,22.042) AW63(-38.628,22.057) AY2(-0.543,22.628) AY62(-38.062,22.628) B2(-0.508,0.508) B63(-38.628,0.592) C1(0,1.137)
  round 0.381 smd: A4(-1.894,0) A5(-2.554,0) A6(-3.75,0) A59(-35.9,0) A60(-36.726,0) A61(-37.386,0) AA9(-5.032,11.576) AA21(-11.688,11.489) AA23(-13.115,11.489) AA58(-35.377,11.33) AB10(-5.476,12.053) AB20(-11.18,11.896) AB21(-11.688,12.302) AB22(-12.607,11.896) AB23(-13.115,12.302) AB57(-35.057,11.98) AC9(-5.032,12.529) AC20(-11.18,12.709) AC22(-12.607,12.709) AC58(-35.377,12.63) AD10(-5.476,13.005) AD21(-11.688,13.115) AD23(-13.115,13.115) AD57(-35.057,13.28) AE9(-5.032,13.481) AE10(-5.476,13.958) AE20(-11.18,13.521) AE21(-11.688,13.928) AE22(-12.607,13.521) AE23(-13.115,13.928) AE58(-35.377,13.931) AF9(-5.032,14.434) AF11(-6.059,14.282) AF12(-6.872,14.282) AF14(-7.685,14.282) AF15(-8.497,14.282) AF17(-9.31,14.282) AF18(-10.123,14.282) AF20(-10.936,14.282) AF22(-12.607,14.334) AG10(-5.653,14.79) AG11(-6.465,14.79) AG13(-7.278,14.79) AG14(-8.091,14.79) AG16(-8.904,14.79) AG17(-9.717,14.79) AG19(-10.529,14.79) AG20(-11.342,14.79) AG23(-13.115,14.741) AG57(-35.057,14.581) AG58(-35.692,15.009) AH22(-12.607,15.147) AH24(-13.92,15.289) AH26(-15.22,15.289) AH28(-16.521,15.289) AH30(-17.821,15.289) AH32(-19.122,15.289) AH34(-20.422,15.289) AH36(-21.723,15.289) AH38(-23.023,15.289) AH40(-24.324,15.289) AH42(-25.624,15.289) AH44(-26.925,15.289) AH46(-28.225,15.289) AH49(-29.526,15.289) AH51(-30.826,15.289) AH53(-32.127,15.289) AH55(-33.427,15.289) AH57(-34.728,15.289) AJ23(-13.115,15.553) AJ25(-14.57,15.614) AJ27(-15.871,15.614) AJ29(-17.171,15.614) AJ31(-18.472,15.614) AJ33(-19.772,15.614) AJ35(-21.073,15.614) AJ37(-22.373,15.614) AJ39(-23.674,15.614) AJ41(-24.974,15.614) AJ43(-26.275,15.614) AJ45(-27.575,15.614) AJ47(-28.875,15.614) AJ50(-30.176,15.614) AJ52(-31.476,15.614) AJ54(-32.777,15.614) AJ56(-34.077,15.614) AJ58(-35.378,15.614) AT1(0,19.997) AT63(-38.628,19.848) AU1(0,20.657) AU63(-38.628,20.673) AV1(0,21.318) AV2(-0.66,21.308) AV62(-37.978,21.318) AV63(-38.628,21.333) AW2(-0.66,21.968) AW3(-1.321,21.968) AW61(-37.328,21.978) AW62(-37.978,21.978) AY3(-1.267,22.628) AY4(-1.928,22.628) AY5(-2.588,22.628) AY59(-36.088,22.628) AY60(-36.748,22.628) AY61(-37.409,22.628) B3(-1.259,0.65) B61(-37.315,0.66) B62(-37.978,0.724) C2(-0.65,1.259) C62(-37.978,1.384) C63(-38.628,1.316) D1(0,1.861) D63(-38.628,1.976) E1(0,2.522) E23(-13.333,2.601) E25(-14.714,2.601) E27(-15.84,2.601) E29(-17.221,2.601) E31(-18.348,2.601) E33(-19.729,2.601) E35(-20.855,2.601) E37(-22.236,2.601) E39(-23.363,2.601) E41(-24.744,2.601) E43(-25.87,2.601) E45(-27.251,2.601) E47(-28.378,2.601) E49(-29.759,2.601) E51(-30.885,2.601) E53(-32.266,2.601) E55(-33.393,2.601) E57(-34.774,2.601) E63(-38.628,2.647) F1(0,3.436) F22(-12.717,3.058) F24(-14.023,3.126) F26(-15.277,3.126) F28(-16.531,3.126) F30(-17.785,3.126) F32(-19.038,3.126) F34(-20.292,3.126) F36(-21.546,3.126) F38(-22.8,3.126) F40(-24.053,3.126) F42(-25.307,3.126) F44(-26.561,3.126) F46(-27.815,3.126) F48(-29.068,3.126) F50(-30.322,3.126) F52(-31.576,3.126) F54(-32.83,3.126) F56(-34.083,3.126) F58(-35.377,3.126) G22(-12.607,3.768) G23(-13.333,3.451) G25(-14.714,3.451) G27(-15.84,3.451) G29(-17.221,3.451) G31(-18.348,3.451) G33(-19.729,3.451) G35(-20.855,3.451) G37(-22.236,3.451) G39(-23.363,3.451) G41(-24.744,3.451) G43(-25.87,3.451) G45(-27.251,3.451) G47(-28.378,3.451) G49(-29.759,3.451) G51(-30.885,3.451) G53(-32.266,3.451) G55(-33.393,3.451) G57(-34.774,3.451) H22(-12.607,4.581) H23(-13.115,4.174) H57(-35.057,4.101) J22(-12.607,5.393) J23(-13.115,4.987) J58(-35.377,4.827) K9(-5.032,5.861) K10(-5.935,5.7) K12(-6.888,5.7) K14(-7.84,5.7) K16(-8.793,5.7) K18(-9.745,5.7) K19(-10.698,5.7) K21(-11.65,5.7) K23(-13.115,5.8) K57(-35.057,5.478) L10(-5.476,6.338) L11(-6.412,6.144) L13(-7.364,6.144) L15(-8.317,6.144) L17(-9.269,6.144) L18(-10.222,6.144) L20(-11.18,6.206) L22(-12.607,6.206) L58(-35.377,6.128) M9(-5.032,6.814) M20(-11.18,7.019) M21(-11.688,6.613) M22(-12.607,7.019) M23(-13.115,6.613) M57(-35.057,6.778) N10(-5.476,7.29) N21(-11.688,7.425) N23(-13.115,7.425) N58(-35.377,7.428) P9(-5.032,7.766) P20(-11.18,7.832) P22(-12.607,7.832) P57(-35.057,8.078) R10(-5.476,8.243) R20(-11.18,8.645) R21(-11.688,8.238) R22(-12.607,8.645) R23(-13.115,8.238) T9(-5.032,8.719) T21(-11.688,9.051) T23(-13.115,9.051) T58(-35.377,8.729) U9(-5.032,9.671) U10(-5.476,9.195) U20(-11.18,9.457) U22(-12.607,9.457) U57(-35.057,9.379) V10(-5.476,10.148) V21(-11.688,9.864) V23(-13.115,9.864) V58(-35.377,10.029) W9(-5.032,10.624) W20(-11.18,10.27) W21(-11.688,10.677) W22(-12.607,10.27) W23(-13.115,10.677) W57(-35.057,10.679) Y10(-5.476,11.1) Y20(-11.18,11.083) Y22(-12.607,11.083)
  round 0.305 smd: A8(-4.538,0) A9(-5.452,0) A11(-6.367,0) A12(-7.116,0) A14(-8.03,0) A15(-8.945,0) A17(-9.694,0) A18(-10.608,0) A20(-11.523,0) A21(-12.272,0) A23(-13.186,0) A24(-14.023,0.325) A25(-14.714,0) A27(-15.84,0) A28(-16.531,0.325) A29(-17.221,0) A31(-18.348,0) A32(-19.038,0.325) A33(-19.729,0) A35(-20.855,0) A36(-21.546,0.325) A37(-22.236,0) A39(-23.363,0) A40(-24.053,0.325) A41(-24.744,0) A43(-25.87,0) A44(-26.561,0.325) A45(-27.251,0) A47(-28.378,0) A48(-29.068,0.325) A49(-29.759,0) A51(-30.885,0) A52(-31.576,0.325) A53(-32.266,0) A55(-33.393,0) A56(-34.083,0.325) A57(-34.774,0) AA1(0,11.717) AA2(-0.65,11.717) AA3(-1.3,11.678) AA4(-1.951,11.678) AA59(-36.027,11.638) AA60(-36.678,11.638) AA61(-37.328,11.638) AA62(-37.978,11.676) AA63(-38.628,11.676) AB5(-2.637,12.053) AB6(-3.287,12.053) AB7(-3.937,12.053) AB8(-4.587,12.053) AC1(0,12.466) AC2(-0.65,12.466) AC3(-1.3,12.504) AC4(-1.951,12.504) AC59(-36.027,12.464) AC60(-36.678,12.464) AC61(-37.328,12.464) AC62(-37.978,12.426) AC63(-38.628,12.426) AD1(0,13.215) AD2(-0.65,13.215) AD3(-1.3,13.177) AD4(-1.951,13.177) AD5(-2.637,13.005) AD6(-3.287,13.005) AD7(-3.937,13.005) AD8(-4.587,13.005) AD59(-36.027,13.137) AD60(-36.678,13.137) AD61(-37.328,13.137) AD62(-37.978,13.175) AD63(-38.628,13.175) AE5(-2.637,13.958) AE6(-3.287,13.958) AE7(-3.937,13.958) AE8(-4.587,13.958) AE59(-36.027,13.962) AE60(-36.678,13.962) AE61(-37.328,13.962) AE62(-37.978,13.924) AE63(-38.628,13.924) AF1(0,13.964) AF2(-0.65,13.964) AF3(-1.3,14.003) AF4(-1.951,14.003) AG1(0,14.714) AG2(-0.65,14.714) AG3(-1.3,14.676) AG4(-1.951,14.676) AG5(-2.637,14.91) AG6(-3.287,14.91) AG7(-3.937,14.91) AG8(-4.587,14.91) AG21(-11.955,15.122) AG60(-36.352,14.602) AG61(-37.003,14.602) AG62(-37.653,14.602) AG63(-38.303,14.602) AH1(0,15.463) AH2(-0.65,15.463) AH3(-1.3,15.501) AH4(-1.951,15.501) AH10(-5.653,15.476) AH11(-6.465,15.476) AH13(-7.278,15.476) AH14(-8.091,15.476) AH16(-8.904,15.476) AH17(-9.717,15.476) AH19(-10.529,15.476) AH20(-11.342,15.476) AH60(-36.678,15.278) AH61(-37.328,15.278) AH62(-37.978,15.278) AH63(-38.628,15.278) AJ5(-2.637,15.863) AJ6(-3.287,15.863) AJ7(-3.937,15.863) AJ8(-4.587,15.863) AJ10(-5.653,16.126) AJ11(-6.465,16.126) AJ13(-7.278,16.126) AJ14(-8.091,16.126) AJ60(-36.352,15.954) AJ61(-37.003,15.954) AJ62(-37.653,15.954) AJ63(-38.303,15.954) AK1(0,16.212) AK2(-0.65,16.212) AK3(-1.3,16.174) AK4(-1.951,16.174) AK8(-4.303,16.451) AK18(-9.848,16.266) AK20(-10.801,16.266) AK21(-11.753,16.266) AK60(-36.678,16.523) AK61(-37.328,16.523) AK62(-37.978,16.629) AK63(-38.628,16.629) AL1(0,16.962) AL2(-0.65,16.962) AL3(-1.3,17) AL4(-1.951,17) AL5(-2.901,16.776) AL7(-3.739,16.776) AL8(-4.303,17.101) AL10(-5.658,16.776) AL11(-6.221,17.101) AL13(-7.576,16.776) AL15(-8.14,17.101) AL17(-9.222,16.583) AL18(-9.848,16.916) AL20(-10.801,16.916) AL21(-11.753,16.916) AL22(-12.706,16.916) AL23(-13.529,16.916) AL25(-14.504,16.916) AL26(-15.456,16.916) AL28(-16.409,16.916) AL29(-17.361,16.916) AL31(-18.26,16.591) AL32(-18.824,16.916) AL33(-19.726,16.916) AL35(-20.729,16.916) AL36(-21.58,16.916) AL38(-22.634,16.916) AL39(-23.542,16.591) AL40(-24.131,16.916) AL42(-24.944,16.916) AL43(-25.897,16.916) AL45(-26.874,16.916) AL46(-27.802,16.916) AL48(-28.856,16.916) AL49(-29.757,16.916) AL51(-30.761,16.916) AL52(-31.583,16.916) AL54(-32.61,16.916) AL55(-33.562,16.916) AL57(-34.509,16.916) AL58(-35.408,16.916) AL60(-36.352,17.169) AL61(-37.003,17.169) AM1(0,17.711) AM2(-0.65,17.711) AM3(-1.3,17.673) AM4(-1.951,17.673) AM5(-2.901,17.426) AM7(-3.739,17.426) AM8(-4.303,17.752) AM10(-5.658,17.426) AM11(-6.221,17.752) AM13(-7.576,17.426) AM15(-8.14,17.752) AM17(-9.222,17.233) AM18(-9.848,17.567) AM20(-10.801,17.567) AM21(-11.753,17.567) AM22(-12.706,17.567) AM23(-13.529,17.567) AM25(-14.504,17.567) AM26(-15.456,17.567) AM28(-16.409,17.567) AM29(-17.361,17.567) AM31(-18.26,17.242) AM32(-18.824,17.567) AM33(-19.726,17.567) AM35(-20.729,17.567) AM36(-21.58,17.567) AM38(-22.634,17.567) AM40(-24.131,17.567) AM42(-24.944,17.567) AM43(-25.897,17.567) AM45(-26.874,17.567) AM46(-27.802,17.567) AM48(-28.856,17.567) AM49(-29.757,17.567) AM51(-30.761,17.567) AM52(-31.583,17.567) AM54(-32.61,17.567) AM55(-33.562,17.567) AM57(-34.509,17.567) AM58(-35.408,17.567) AM60(-36.678,17.816) AM61(-37.328,17.816) AM62(-37.978,17.709) AM63(-38.628,17.709) AN1(0,18.46) AN2(-0.65,18.46) AN3(-1.3,18.498) AN4(-1.951,18.498) AN5(-2.901,18.077) AN7(-3.739,18.077) AN8(-4.303,18.402) AN10(-5.658,18.077) AN11(-6.221,18.402) AN13(-7.576,18.077) AN15(-8.14,18.402) AN17(-9.222,17.883) AN18(-9.848,18.217) AN20(-10.801,18.217) AN21(-11.753,18.217) AN22(-12.706,18.217) AN23(-13.529,18.217) AN25(-14.504,18.217) AN26(-15.456,18.217) AN28(-16.409,18.217) AN29(-17.361,18.217) AN31(-18.26,17.892) AN32(-18.824,18.217) AN33(-19.726,18.217) AN35(-20.729,18.217) AN36(-21.58,18.217) AN38(-22.634,18.217) AN39(-23.542,17.892) AN40(-24.131,18.217) AN42(-24.944,18.217) AN43(-25.897,18.217) AN45(-26.874,18.217) AN46(-27.802,18.217) AN48(-28.856,18.217) AN49(-29.757,18.217) AN51(-30.761,18.217) AN52(-31.583,18.217) AN54(-32.61,18.217) AN55(-33.562,18.217) AN57(-34.509,18.217) AN58(-35.408,18.217) AN60(-36.352,18.385) AN61(-37.003,18.385) AN62(-37.653,18.385) AN63(-38.303,18.385) AP1(0,19.21) AP2(-0.65,19.21) AP3(-1.3,19.171) AP4(-1.951,19.171) AP5(-2.901,18.727) AP7(-3.739,18.727) AP8(-4.303,19.052) AP10(-5.658,18.727) AP11(-6.221,19.052) AP13(-7.576,18.727) AP15(-8.14,19.052) AP17(-9.222,18.533) AP18(-9.848,18.867) AP20(-10.801,18.867) AP21(-11.753,18.867) AP22(-12.706,18.867) AP23(-13.529,18.867) AP25(-14.504,18.867) AP26(-15.456,18.867) AP28(-16.409,18.867) AP29(-17.361,18.867) AP31(-18.26,18.542) AP32(-18.824,18.867) AP33(-19.726,18.867) AP35(-20.729,18.867) AP36(-21.58,18.867) AP38(-22.634,18.867) AP39(-23.542,18.542) AP40(-24.131,18.867) AP42(-24.944,18.867) AP43(-25.897,18.867) AP45(-26.874,18.867) AP46(-27.802,18.867) AP48(-28.856,18.867) AP49(-29.757,18.867) AP51(-30.761,18.867) AP52(-31.583,18.867) AP54(-32.61,18.867) AP55(-33.562,18.867) AP57(-34.509,18.867) AP58(-35.408,18.867) AP60(-36.678,19.06) AP61(-37.328,19.06) AP62(-37.978,19.06) AP63(-38.628,19.06) AR5(-2.901,19.377) AR7(-3.739,19.377) AR8(-4.303,19.702) AR10(-5.658,19.377) AR11(-6.221,19.702) AR13(-7.576,19.377) AR15(-8.14,19.702) AR17(-9.222,19.184) AR18(-9.848,19.517) AR20(-10.801,19.517) AR21(-11.753,19.517) AR22(-12.706,19.517) AR23(-13.529,19.517) AR25(-14.504,19.517) AR26(-15.456,19.517) AR28(-16.409,19.517) AR29(-17.361,19.517) AR31(-18.26,19.192) AR32(-18.824,19.517) AR33(-19.726,19.517) AR35(-20.729,19.517) AR36(-21.58,19.517) AR38(-22.634,19.517) AR39(-23.542,19.192) AR40(-24.131,19.517) AR42(-24.944,19.517) AR43(-25.897,19.517) AR45(-26.874,19.517) AR46(-27.802,19.517) AR48(-28.856,19.517) AR49(-29.757,19.517) AR51(-30.761,19.517) AR52(-31.583,19.517) AR54(-32.61,19.517) AR55(-33.562,19.517) AR57(-34.509,19.517) AR58(-35.408,19.517) AT2(-0.65,19.959) AT3(-1.3,19.997) AT4(-1.951,19.997) AT5(-2.901,20.027) AT7(-3.739,20.027) AT10(-5.658,20.027) AT13(-7.576,20.027) AT35(-20.437,20.22) AT37(-22.011,20.22) AT40(-23.586,20.22) AT42(-25.161,20.22) AT43(-26.736,20.22) AT46(-28.311,20.22) AT49(-29.912,20.248) AT61(-37.003,19.634) AT62(-37.812,19.69) AU2(-0.655,20.647) AU3(-1.315,20.647) AU4(-1.976,20.647) AU6(-3.337,20.678) AU7(-4.163,20.678) AU8(-4.836,20.678) AU10(-5.661,20.678) AU11(-6.335,20.678) AU12(-7.16,20.678) AU14(-7.833,20.678) AU15(-8.659,20.678) AU16(-9.222,20.353) AU17(-9.86,20.678) AU18(-10.536,20.353) AU19(-11.105,20.678) AU20(-11.751,20.353) AU21(-12.397,20.678) AU22(-12.966,20.353) AU23(-13.642,20.678) AU24(-14.318,20.353) AU25(-14.993,20.678) AU26(-15.669,20.353) AU27(-16.238,20.678) AU28(-16.884,20.353) AU29(-17.531,20.678) AU30(-18.1,20.353) AU31(-18.775,20.678) AU33(-19.372,20.33) AU34(-19.974,20.678) AU35(-20.899,20.678) AU36(-21.549,20.678) AU37(-22.474,20.678) AU39(-23.124,20.678) AU40(-24.048,20.678) AU41(-24.699,20.678) AU42(-25.623,20.678) AU43(-26.274,20.678) AU44(-27.198,20.678) AU46(-27.848,20.678) AU47(-28.773,20.678) AU49(-29.423,20.678) AU50(-30.4,20.678) AU51(-30.98,20.353) AU52(-31.656,20.678) AU53(-32.331,20.353) AU54(-32.9,20.678) AU55(-33.547,20.353) AU56(-34.193,20.678) AU57(-34.762,20.353) AU58(-35.438,20.678) AU59(-36.002,20.353) AU60(-36.566,20.678) AU61(-37.277,20.401) AU62(-37.978,20.663) AV3(-1.321,21.308) AV4(-1.976,21.308) AV5(-2.664,21.328) AV6(-3.337,21.328) AV7(-4.163,21.328) AV8(-4.836,21.328) AV10(-5.661,21.328) AV11(-6.335,21.328) AV12(-7.16,21.328) AV14(-7.833,21.328) AV15(-8.659,21.328) AV16(-9.222,21.003) AV17(-9.86,21.328) AV18(-10.536,21.003) AV19(-11.105,21.328) AV20(-11.751,21.003) AV21(-12.397,21.328) AV22(-12.966,21.003) AV23(-13.642,21.328) AV24(-14.318,21.003) AV25(-14.993,21.328) AV26(-15.669,21.003) AV27(-16.238,21.328) AV28(-16.884,21.003) AV29(-17.531,21.328) AV30(-18.1,21.003) AV31(-18.775,21.328) AV33(-19.4,21.003) AV34(-20.024,21.328) AV35(-20.849,21.328) AV36(-21.599,21.328) AV37(-22.424,21.328) AV39(-23.173,21.328) AV40(-23.999,21.328) AV41(-24.748,21.328) AV42(-25.574,21.328) AV43(-26.323,21.328) AV44(-27.149,21.328) AV46(-27.898,21.328) AV47(-28.723,21.328) AV49(-29.473,21.328) AV50(-30.298,21.328) AV51(-30.98,21.003) AV52(-31.656,21.328) AV53(-32.331,21.003) AV54(-32.9,21.328) AV55(-33.547,21.003) AV56(-34.193,21.328) AV57(-34.762,21.003) AV58(-35.438,21.328) AV59(-36.002,21.003) AV60(-36.566,21.328) AV61(-37.302,21.051) AW4(-1.976,21.968) AW5(-2.626,21.978) AW6(-3.375,21.978) AW7(-4.125,21.978) AW8(-4.874,21.978) AW10(-5.623,21.978) AW11(-6.373,21.978) AW12(-7.122,21.978) AW14(-7.871,21.978) AW15(-8.621,21.978) AW16(-9.222,21.653) AW17(-9.86,21.978) AW18(-10.536,21.653) AW19(-11.211,21.978) AW21(-12.291,21.978) AW22(-12.966,21.653) AW23(-13.642,21.978) AW24(-14.318,21.653) AW25(-14.993,21.978) AW26(-15.669,21.653) AW27(-16.345,21.978) AW29(-17.424,21.978) AW30(-18.1,21.653) AW31(-18.775,21.978) AW33(-19.451,21.653) AW34(-20.024,21.978) AW35(-20.849,21.978) AW36(-21.599,21.978) AW37(-22.424,21.978) AW39(-23.173,21.978) AW40(-23.999,21.978) AW41(-24.748,21.978) AW42(-25.574,21.978) AW43(-26.323,21.978) AW44(-27.149,21.978) AW46(-27.898,21.978) AW47(-28.723,21.978) AW49(-29.473,21.978) AW50(-30.298,21.978) AW51(-30.98,21.653) AW52(-31.656,21.978) AW53(-32.331,21.653) AW54(-33.007,21.978) AW56(-34.087,21.978) AW57(-34.762,21.653) AW58(-35.438,21.978) AW59(-36.002,21.653) AW60(-36.566,21.978) AY6(-3.375,22.628) AY7(-4.125,22.628) AY8(-4.874,22.628) AY10(-5.623,22.628) AY11(-6.373,22.628) AY12(-7.122,22.628) AY14(-7.871,22.628) AY15(-8.621,22.628) AY16(-9.184,22.303) AY17(-9.86,22.628) AY18(-10.536,22.303) AY19(-11.211,22.628) AY21(-12.291,22.628) AY22(-12.966,22.303) AY23(-13.642,22.628) AY24(-14.318,22.303) AY25(-14.993,22.628) AY26(-15.669,22.303) AY27(-16.345,22.628) AY29(-17.424,22.628) AY30(-18.1,22.303) AY31(-18.775,22.628) AY33(-19.451,22.303) AY34(-20.024,22.628) AY35(-20.849,22.628) AY36(-21.599,22.628) AY37(-22.424,22.628) AY39(-23.173,22.628) AY40(-23.999,22.628) AY41(-24.748,22.628) AY42(-25.574,22.628) AY43(-26.323,22.628) AY44(-27.149,22.628) AY46(-27.898,22.628) AY47(-28.723,22.628) AY49(-29.473,22.628) AY50(-30.298,22.628) AY51(-30.98,22.303) AY52(-31.656,22.628) AY53(-32.331,22.303) AY54(-33.007,22.628) AY56(-34.087,22.628) AY57(-34.762,22.303) AY58(-35.438,22.628) B4(-1.922,0.65) B5(-3.138,0.643) B6(-4.119,0.643) B8(-4.891,0.643) B9(-5.716,0.643) B11(-6.697,0.643) B12(-7.469,0.643) B14(-8.294,0.643) B15(-9.275,0.643) B17(-10.047,0.643) B18(-10.872,0.643) B20(-11.853,0.643) B21(-12.272,1.196) B22(-12.625,0.643) B23(-13.451,0.643) B24(-14.023,0.975) B25(-14.714,0.65) B26(-15.277,0.975) B27(-15.84,0.65) B28(-16.531,0.975) B29(-17.221,0.65) B30(-17.785,0.975) B31(-18.348,0.65) B32(-19.038,0.975) B33(-19.729,0.65) B34(-20.292,0.975) B35(-20.855,0.65) B36(-21.546,0.975) B37(-22.236,0.65) B38(-22.8,0.975) B39(-23.363,0.65) B40(-24.053,0.975) B41(-24.744,0.65) B42(-25.307,0.975) B43(-25.87,0.65) B44(-26.561,0.975) B45(-27.251,0.65) B46(-27.815,0.975) B47(-28.378,0.65) B48(-29.068,0.975) B49(-29.759,0.65) B50(-30.322,0.975) B51(-30.885,0.65) B52(-31.576,0.975) B53(-32.266,0.65) B54(-32.83,0.975) B55(-33.393,0.65) B56(-34.083,0.975) B57(-34.774,0.65) B58(-35.337,0.975) B59(-35.9,0.65) B60(-36.665,0.66) C3(-1.302,1.302) C4(-2.118,1.272) C5(-2.772,1.196) C6(-3.776,1.196) C8(-4.538,1.196) C9(-5.351,1.196) C11(-6.354,1.196) C12(-7.116,1.196) C14(-7.929,1.196) C15(-8.932,1.196) C17(-9.694,1.196) C18(-10.507,1.196) C20(-11.51,1.196) C21(-11.891,1.786) C22(-12.678,1.786) C23(-13.085,1.196) C24(-14.051,2.032) C25(-14.714,1.3) C26(-15.277,1.626) C27(-15.84,1.3) C28(-16.558,2.032) C29(-17.221,1.3) C30(-17.785,1.626) C31(-18.348,1.3) C32(-19.066,2.032) C33(-19.729,1.3) C34(-20.292,1.626) C35(-20.855,1.3) C36(-21.573,2.032) C37(-22.236,1.3) C38(-22.8,1.626) C39(-23.363,1.3) C40(-24.081,2.032) C41(-24.744,1.3) C42(-25.307,1.626) C43(-25.87,1.3) C44(-26.588,2.032) C45(-27.251,1.3) C46(-27.815,1.626) C47(-28.378,1.3) C48(-29.07,2.032) C49(-29.759,1.3) C50(-30.322,1.626) C51(-30.885,1.3) C52(-31.578,1.991) C53(-32.266,1.3) C54(-32.83,1.626) C55(-33.393,1.3) C56(-34.085,1.991) C57(-34.774,1.3) C58(-35.337,1.626) C59(-35.9,1.3) C61(-37.003,1.237) D2(-0.65,2.075) D3(-1.3,2.037) D5(-2.678,1.842) D6(-3.369,1.786) D8(-4.157,1.786) D9(-4.944,1.786) D11(-5.852,1.786) D12(-6.735,1.786) D14(-7.522,1.786) D15(-8.43,1.786) D17(-9.313,1.786) D18(-10.1,1.786) D20(-11.008,1.786) D21(-12.235,2.423) D23(-13.377,1.786) D25(-14.714,1.951) D26(-15.277,2.276) D27(-15.84,1.951) D29(-17.221,1.951) D30(-17.785,2.276) D31(-18.348,1.951) D33(-19.729,1.951) D34(-20.292,2.276) D35(-20.855,1.951) D37(-22.236,1.951) D38(-22.8,2.276) D39(-23.363,1.951) D41(-24.744,1.951) D42(-25.307,2.276) D43(-25.87,1.951) D45(-27.251,1.951) D46(-27.815,2.276) D47(-28.378,1.951) D49(-29.759,1.951) D50(-30.322,2.276) D51(-30.885,1.951) D53(-32.266,1.951) D54(-32.83,2.276) D55(-33.393,1.951) D57(-34.774,1.951) D58(-35.337,2.276) D59(-35.9,1.951) D60(-36.678,1.801) D61(-37.328,1.801) D62(-37.978,2.035) E2(-0.65,2.725) E3(-1.3,2.687) E4(-1.951,2.687) E5(-2.602,2.619) E6(-3.554,2.619) E8(-4.507,2.619) E10(-5.459,2.619) E11(-6.412,2.619) E13(-7.364,2.619) E15(-8.317,2.619) E17(-9.269,2.619) E18(-10.222,2.619) E20(-11.174,2.619) E59(-36.027,2.647) E60(-36.678,2.647) E61(-37.328,2.647) E62(-37.978,2.685) F2(-0.65,3.474) F3(-1.3,3.512) F4(-1.951,3.512) F5(-2.602,3.269) F6(-3.554,3.269) F8(-4.507,3.269) F10(-5.459,3.269) F11(-6.412,3.269) F13(-7.364,3.269) F15(-8.317,3.269) F17(-9.269,3.269) F18(-10.222,3.269) F20(-11.174,3.269) F59(-36.027,3.472) F60(-36.678,3.472) F61(-37.328,3.472) F62(-37.978,3.434) F63(-38.628,3.434) G1(0,4.224) G2(-0.65,4.224) G3(-1.3,4.185) G4(-1.951,4.185) G5(-2.602,3.919) G6(-3.554,3.919) G8(-4.507,3.919) G10(-5.459,3.919) G11(-6.412,3.919) G13(-7.364,3.919) G15(-8.317,3.919) G17(-9.269,3.919) G18(-10.222,3.919) G20(-11.174,3.919) H5(-2.602,4.569) H6(-3.554,4.569) H8(-4.507,4.569) H10(-5.459,4.569) H11(-6.412,4.569) H13(-7.364,4.569) H15(-8.317,4.569) H17(-9.269,4.569) H18(-10.222,4.569) H20(-11.174,4.569) H59(-36.027,4.145) H60(-36.678,4.145) H61(-37.328,4.145) H62(-37.978,4.183) H63(-38.628,4.183) J1(0,4.973) J2(-0.65,4.973) J3(-1.3,5.011) J4(-1.951,5.011) J5(-2.627,5.22) J6(-3.567,5.22) J8(-4.507,5.22) J10(-5.459,5.22) J11(-6.412,5.22) J13(-7.364,5.22) J15(-8.317,5.22) J17(-9.269,5.22) J18(-10.222,5.22) J20(-11.174,5.22) J21(-12.095,4.986) J59(-36.027,4.971) J60(-36.678,4.971) J61(-37.328,4.971) J62(-37.978,4.933) J63(-38.628,4.933) K1(0,5.722) K2(-0.65,5.722) K3(-1.3,5.684) K4(-1.951,5.684) K59(-36.027,5.644) K60(-36.678,5.644) K61(-37.328,5.644) K62(-37.978,5.682) K63(-38.628,5.682) L1(0,6.471) L2(-0.65,6.471) L3(-1.3,6.51) L4(-1.951,6.51) L5(-2.637,6.338) L6(-3.287,6.338) L7(-3.937,6.338) L8(-4.587,6.338) L59(-36.027,6.469) L60(-36.678,6.469) L61(-37.328,6.469) L62(-37.978,6.431) L63(-38.628,6.431) N1(0,7.221) N2(-0.65,7.221) N3(-1.3,7.183) N4(-1.951,7.183) N5(-2.637,7.29) N6(-3.287,7.29) N7(-3.937,7.29) N8(-4.587,7.29) N59(-36.027,7.142) N60(-36.678,7.142) N61(-37.328,7.142) N62(-37.978,7.181) N63(-38.628,7.181) P1(0,7.97) P2(-0.65,7.97) P3(-1.3,8.008) P4(-1.951,8.008) P59(-36.027,7.968) P60(-36.678,7.968) P61(-37.328,7.968) P62(-37.978,7.93) P63(-38.628,7.93) R5(-2.637,8.243) R6(-3.287,8.243) R7(-3.937,8.243) R8(-4.587,8.243) T1(0,8.719) T2(-0.65,8.719) T3(-1.3,8.681) T4(-1.951,8.681) T59(-36.027,8.641) T60(-36.678,8.641) T61(-37.328,8.641) T62(-37.978,8.679) T63(-38.628,8.679) U1(0,9.469) U2(-0.65,9.469) U3(-1.3,9.507) U4(-1.951,9.507) U5(-2.637,9.195) U6(-3.287,9.195) U7(-3.937,9.195) U8(-4.587,9.195) U59(-36.027,9.467) U60(-36.678,9.467) U61(-37.328,9.467) U62(-37.978,9.428) U63(-38.628,9.428) V1(0,10.218) V2(-0.65,10.218) V3(-1.3,10.18) V4(-1.951,10.18) V5(-2.637,10.148) V6(-3.287,10.148) V7(-3.937,10.148) V8(-4.587,10.148) V59(-36.027,10.14) V60(-36.678,10.14) V61(-37.328,10.14) V62(-37.978,10.178) V63(-38.628,10.178) Y1(0,10.967) Y2(-0.65,10.967) Y3(-1.3,11.005) Y4(-1.951,11.005) Y5(-2.637,11.1) Y6(-3.287,11.1) Y7(-3.937,11.1) Y8(-4.587,11.1) Y59(-36.027,10.965) Y60(-36.678,10.965) Y61(-37.328,10.965) Y62(-37.978,10.927) Y63(-38.628,10.927)
  round 0.33 smd: AK22(-12.655,16.266) AK23(-13.529,16.266) AK25(-14.504,16.266) AK26(-15.456,16.266) AK28(-16.409,16.266) AK29(-17.311,16.266) AK32(-18.824,16.266) AK33(-19.726,16.266) AK35(-20.729,16.266) AK36(-21.58,16.266) AK38(-22.609,16.266) AK40(-24.106,16.266) AK42(-24.944,16.266) AK43(-25.897,16.266) AK45(-26.874,16.266) AK46(-27.776,16.266) AK48(-28.83,16.266) AK49(-29.732,16.266) AK51(-30.735,16.266) AK52(-31.583,16.266) AK54(-32.61,16.266) AK55(-33.562,16.266) AK57(-34.509,16.266) AK58(-35.408,16.266)
SHORTPADS
  custom 0.19x0.19 smd: 1(-0.483,0) 2(0.483,0)
SI1553CDL-T1-GE3_SC70-6
  oval 0.406x0.66 smd: 1(0,0) 2(0.65,0) 3(1.3,0) 4(1.3,1.791) 5(0.65,1.791) 6(0,1.791)
SI3457BDV-T1-E3_TSOP6
  oval 0.508x1.448 smd: 1(0,0) 2(1,0) 3(2,0) 4(2,2.425) 5(1,2.425) 6(0,2.425)
SI7716ADN-T1-GE3_POWERPAK8-5
  oval 0.406x0.991 smd: 1(0,0) 2(0.66,0) 3(1.32,0) 4(1.98,0)
  custom 0.559x0.559 smd: 5(0.99,2.247)
SINGA_2SJ3061-030111F_6P-T
  oval 0.991x1.803 hole 0.61x1.397: 1(0,0) 2(8.8,-4.75) 3(0,-7) 4(8.8,-7) 5(8.8,0) 6(8.8,-2.55) 7(0,-3.3)
SIR472DP-T1-GE3_POWERPAK8-5
  oval 0.61x1.27 smd: 1(0,0) 2(1.27,0) 3(2.54,0) 4(3.81,0)
  custom 1.105x1.105 smd: 5(1.905,3.36)
SIS412DN-T1-GE3_POWERPAK8-5
  oval 0.406x0.991 smd: 1(0,0) 2(0.66,0) 3(1.32,0) 4(1.98,0)
  custom 0.559x0.559 smd: 5(0.99,2.247)
SN74AHC1G04DCKR_SOT23-5
  oval 0.356x1.219 smd: 1(0,0) 2(0.65,0) 3(1.3,0) 4(1.3,1.675) 5(0,1.675)
SN74AHC1G08DCKR_SC70-5
  oval 0.381x1.295 smd: 1(0,0.15) 2(0.65,0.15) 3(1.3,0.15) 4(1.3,1.89) 5(0,1.89)
SN74AHC1G32DCKR_SC70-5
  oval 0.457x0.711 smd: 1(0,0) 2(0.65,0) 3(1.3,0) 4(1.3,1.85) 5(0,1.85)
SN74CBT1G125DCKR_SC70-5
  oval 0.381x0.864 smd: 1(0,0) 2(0.65,0) 3(1.3,0) 4(1.3,1.74) 5(0,1.74)
SN74LVC1G06DCKR_SC70-5
  oval 0.381x0.864 smd: 1(0,0) 2(0.65,0) 3(1.3,0) 4(1.3,1.74) 5(0,1.74)
SSM3K7002FU_SC70-3
  oval 0.508x0.991 smd: 1(0,0) 2(0.65,1.9) 3(-0.65,1.9)
STARC_300E50-0011RA-G3_50P
  oval 0.254x1.092 smd: 1(0,0) 2(0.5,0) 3(1,0) 4(1.5,0) 5(2,0) 6(2.5,0) 7(3,0) 8(3.5,0) 9(4,0) 10(4.5,0) 11(5,0) 12(5.5,0) 13(6,0) 14(6.5,0) 15(7,0) 16(7.5,0) 17(8,0) 18(8.5,0) 19(9,0) 20(9.5,0) 21(10,0) 22(10.5,0) 23(11,0) 24(11.5,0) 25(12,0) 26(12.5,0) 27(13,0) 28(13.5,0) 29(14,0) 30(14.5,0) 31(15,0) 32(15.5,0) 33(16,0) 34(16.5,0) 35(17,0) 36(17.5,0) 37(18,0) 38(18.5,0) 39(19,0) 40(19.5,0) 41(20,0) 42(20.5,0) 43(21,0) 44(21.5,0) 45(22,0) 46(22.5,0) 47(23,0) 48(23.5,0) 49(24,0) 50(24.5,0)
  rect 0.559x1.092 smd: 51(-0.9,0) 53(25.4,0)
  rect 1.397x1.905 smd: 52(-3.1,-2.92) 54(27.6,-2.92)
STM32F103RDY6TR_WLCSP_64P
  round 0.254 smd: A1(0,0) A2(0.5,0) A3(1,0) A4(1.5,0) A5(2,0) A6(2.5,0) A7(3,0) A8(3.5,0) B1(0,-0.5) B2(0.5,-0.5) B3(1,-0.5) B4(1.5,-0.5) B5(2,-0.5) B6(2.5,-0.5) B7(3,-0.5) B8(3.5,-0.5) C1(0,-1) C2(0.5,-1) C3(1,-1) C4(1.5,-1) C5(2,-1) C6(2.5,-1) C7(3,-1) C8(3.5,-1) D1(0,-1.5) D2(0.5,-1.5) D3(1,-1.5) D4(1.5,-1.5) D5(2,-1.5) D6(2.5,-1.5) D7(3,-1.5) D8(3.5,-1.5) E1(0,-2) E2(0.5,-2) E3(1,-2) E4(1.5,-2) E5(2,-2) E6(2.5,-2) E7(3,-2) E8(3.5,-2) F1(0,-2.5) F2(0.5,-2.5) F3(1,-2.5) F4(1.5,-2.5) F5(2,-2.5) F6(2.5,-2.5) F7(3,-2.5) F8(3.5,-2.5) G1(0,-3) G2(0.5,-3) G3(1,-3) G4(1.5,-3) G5(2,-3) G6(2.5,-3) G7(3,-3) G8(3.5,-3) H1(0,-3.5) H2(0.5,-3.5) H3(1,-3.5) H4(1.5,-3.5) H5(2,-3.5) H6(2.5,-3.5) H7(3,-3.5) H8(3.5,-3.5)
SW_T3AL-23-Q-T-R_4P
  rect 0.66x0.711 smd: 1(0,0) 2(2.95,0) 3(0,-1.9) 4(2.95,-1.9)
SW_WCM2012F2S_4P
  rect 0.889x0.406 smd: 1(0,0) 2(1.7,0) 3(1.7,-0.8) 4(0,-0.8)
SX34H_SMA2
  rect 2.057x2.057 smd: 1(0,0) 2(3.73,0)
T-SOL_156-2001302603_19P-T
  round 0.889 hole 0.889 unplated: (-4.5,0.35) (20.8,0.35)
  oval 0.787x1.499 smd: 1(0,0) 2(1.4,0) 3(2.8,0) 4(4.2,0) 5(5.6,0) 6(9.75,0) 7(12.55,0) 8(11.15,0) 9(13.95,0) 10(15.35,0) 11(16.75,0)
  oval 1.499x0.787 smd: 12(-6.25,-19.05) 13(-6.25,-20.15) 14(-6.25,-21.25) 15(-6.25,-22.35) 16(22.55,-22.35) 17(22.55,-21.25) 18(22.55,-20.15) 19(22.55,-19.05)
  rect 1.6x1.499 smd: 20(22.6,-16.25) 21(22.6,-5.4) 22(-6.3,-5.4) 23(-6.3,-16.25)
TAI-T_HCB2012KF-121T50_2P
  rect 0.991x0.991 smd: 1(0,0) 2(2,0)
TAIWI_USB022-107CRL-TW_10P-T
  round 1.194 hole 0.787: 1(0,0) 2(2.5,0) 3(4.5,0) 4(7,0) 5(7.5,1.5) 6(5.5,1.5) 7(3.5,1.5) 8(1.5,1.5) 9(-0.5,1.5)
  round 1.067 hole 0.762: 10(-1.37,0)
  oval 1.549x2.464 hole 0.787x1.702: 11(-4.75,-6.78) 12(-2.9,-0.23) 13(9.9,-0.23) 14(11.35,-6.78)
TAIYO_NRS4018T1R0NDGJ_2P
  rect 1.194x3.708 smd: 1(0,0) 2(2.8,0)
TLV62150RGTR_QFN16_3X3
  oval 0.254x1.016 smd: 1(0,0) 2(0.5,0) 3(1,0) 4(1.5,0) 9(1.5,2.975) 10(1,2.975) 11(0.5,2.975) 12(0,2.975)
  oval 1.016x0.254 smd: 5(2.238,0.738) 6(2.238,1.238) 7(2.238,1.738) 8(2.238,2.238) 13(-0.738,2.238) 14(-0.738,1.738) 15(-0.738,1.238) 16(-0.738,0.738)
  rect 1.702x1.702 smd: 17(0.75,1.488)
TOKO_FDSD0630-H-2R2M-P3_2P
  rect 2.159x3.505 smd: 1(0,0) 2(5.85,0)
TOKO_FDSD0630-H-3R3M-P3_2P
  rect 2.159x3.505 smd: 1(0,0) 2(5.85,0)
TPC12
  round 0.305 smd: 1(0,0)
TPS2543RTER_QFN16_3X3
  oval 0.254x1.016 smd: 1(0,0) 2(0.5,0) 3(1,0) 4(1.5,0) 9(1.5,2.975) 10(1,2.975) 11(0.5,2.975) 12(0,2.975)
  oval 1.016x0.254 smd: 5(2.238,0.738) 6(2.238,1.238) 7(2.238,1.738) 8(2.238,2.238) 13(-0.738,2.238) 14(-0.738,1.738) 15(-0.738,1.238) 16(-0.738,0.738)
  rect 1.702x1.702 smd: 17(0.75,1.488)
TPS22965DSGR_SON8_2X2
  oval 0.254x0.787 smd: 1(0,0) 2(0.5,0) 3(1,0) 4(1.5,0) 5(1.5,2.2) 6(1,2.2) 7(0.5,2.2) 8(0,2.2)
  rect 1.6x0.889 smd: 9(0.75,1.1)
TPS22966DPUR_SON14_2X3
  oval 0.203x0.762 smd: 1(0,0) 2(0.4,0) 3(0.8,0) 4(1.2,0) 5(1.6,0) 6(2,0) 7(2.4,0) 8(2.4,2.05) 9(2,2.05) 10(1.6,2.05) 11(1.2,2.05) 12(0.8,2.05) 13(0.4,2.05) 14(0,2.05)
  rect 2.489x0.889 smd: 15(1.2,1.025)
